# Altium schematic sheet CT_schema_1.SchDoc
size 421 x 258 mm
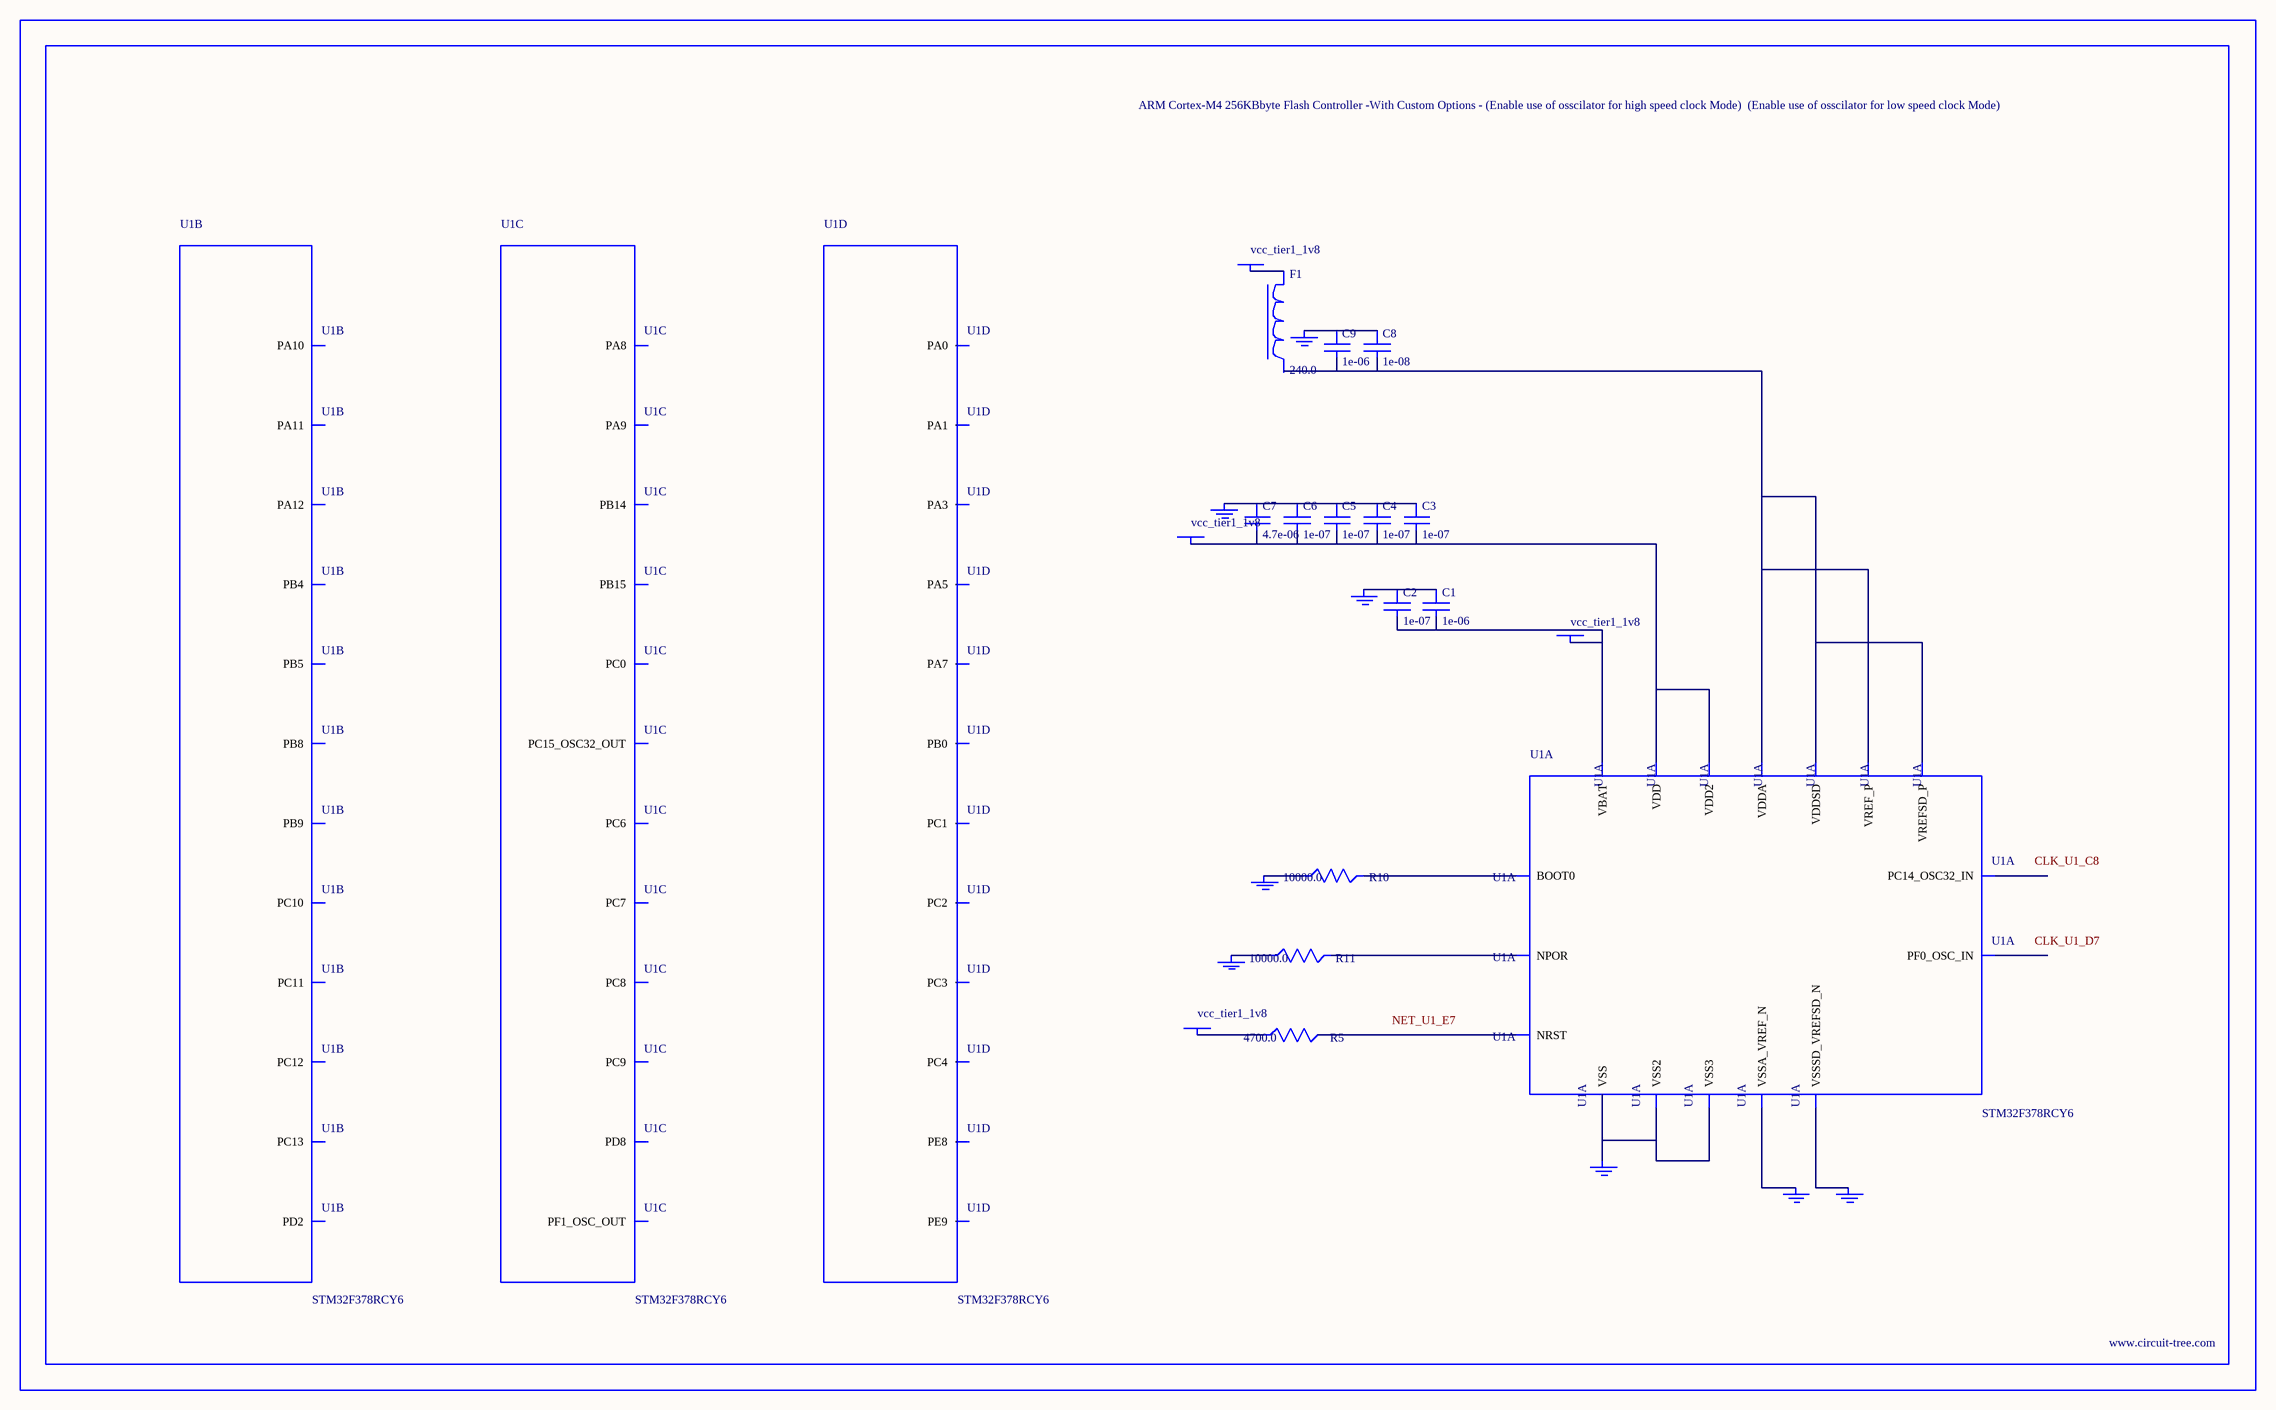
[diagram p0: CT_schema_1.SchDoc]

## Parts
BORDER0  (no value)
C1  1e-06  [C0603]
C2  1e-07  [C0603]
C3  1e-07  [C0603]
C4  1e-07  [C0603]
C5  1e-07  [C0603]
C6  1e-07  [C0603]
C7  4.7e-06  [C0603]
C8  1e-08  [C0603]
C9  1e-06  [C0603]
F1  240.0  [L0603]
GND_INSTANCE_0_0  (no value)
GND_INSTANCE_0_1  (no value)
GND_INSTANCE_0_2  (no value)
GND_INSTANCE_0_3  (no value)
GND_INSTANCE_0_4  (no value)
GND_INSTANCE_0_5  (no value)
GND_INSTANCE_0_6  (no value)
GND_INSTANCE_0_7  (no value)
POWER_INSTANCE_0_0  vcc_tier1_1v8
POWER_INSTANCE_0_1  vcc_tier1_1v8
POWER_INSTANCE_0_2  vcc_tier1_1v8
POWER_INSTANCE_0_3  vcc_tier1_1v8
R5  4700.0  [R0603]
R10  10000.0  [R0603]
R11  10000.0  [R0603]
U1  STM32F378RCY6  [WLCSP66_8X8]  (parts A,B,C,D of 6)

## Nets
NetC1_1: C1.1 C2.1 GND_INSTANCE_0_0.0(GND)
NetC1_2: C1.2 C2.2 POWER_INSTANCE_0_0.0(PWR) U1.A8(VBAT)
NetC3_1: C3.1 C4.1 C5.1 C6.1 C7.1 GND_INSTANCE_0_2.0(GND)
NetC3_2: C3.2 C4.2 C5.2 C6.2 C7.2 POWER_INSTANCE_0_2.0(PWR) U1.D6(VDD) U1.J7(VDD2)
NetC8_1: C8.1 C9.1 GND_INSTANCE_0_1.0(GND)
NetC8_2: C8.2 C9.2 U1.G1(VREFSD_P) U1.G6(VREF_P) U1.G7(VDDA) U1.H1(VDDSD)
NetF1_1: F1.1 POWER_INSTANCE_0_1.0(PWR)
NetGND_INSTANCE_0_3_0: GND_INSTANCE_0_3.0(GND) R10.1
NetGND_INSTANCE_0_4_0: GND_INSTANCE_0_4.0(GND) R11.1
NetGND_INSTANCE_0_5_0: GND_INSTANCE_0_5.0(GND) U1.G8(VSSA_VREF_N)
NetGND_INSTANCE_0_6_0: GND_INSTANCE_0_6.0(GND) U1.J1(VSSSD_VREFSD_N)
NetGND_INSTANCE_0_7_0: GND_INSTANCE_0_7.0(GND) U1.C6(VSS) U1.G4(VSS2) U1.G5(VSS3)
NetPOWER_INSTANCE_0_3_0: POWER_INSTANCE_0_3.0(PWR) R5.1
NetR5_2: R5.2 U1.E7(NRST)
NetR10_2: R10.2 U1.C7(BOOT0)
NetR11_2: R11.2 U1.G2(NPOR)

Not connected (* = marked no-connect by the designer): F1 2; U1 A3(PC11) A4(PD2) A5(PB5) A7(PB9) B3(PC10) B4(PC12) B5(PB4) B7(PB8) B8(PC13) C1(PA11) C2(PA10) C3(PA12) C8(PC14_OSC32_IN) D1(PA8) D2(PC9) D3(PA9) D7(PF0_OSC_IN) D8(PC15_OSC32_OUT) E1(PC7) E2(PC6) E3(PC8) E6(PC0) E8(PF1_OSC_OUT) F1(PB15) F2(PB14) F3(PD8) F6(PC3) F7(PC2) F8(PC1) G3(PA7) H2(PE8) H3(PB0) H4(PC4) H5(PA5) H6(PA3) H7(PA1) H8(PA0) J2(PE9)

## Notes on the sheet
- Labels drawn without touching a wire or pin: CLK_U1_C8, CLK_U1_D7, NET_U1_E7

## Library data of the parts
BORDER0 = BORDER_PAGE0
C1 C9 = C0603C105K3RACTU
C2-C6 = 06035C104K4Z2A
C7 = GRM188R6YA475KE15D
C8 = 06035C103K4Z2A
F1 = Z0603C241ASMST
GND_INSTANCE_0_0-GND_INSTANCE_0_7 = GND
POWER_INSTANCE_0_0-POWER_INSTANCE_0_3 = PWR
R5 = RC0603JR-074K7L
R10 R11 = RC0603JR-0710KL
